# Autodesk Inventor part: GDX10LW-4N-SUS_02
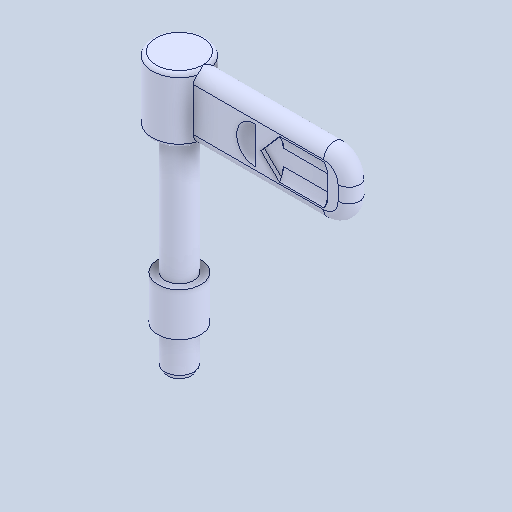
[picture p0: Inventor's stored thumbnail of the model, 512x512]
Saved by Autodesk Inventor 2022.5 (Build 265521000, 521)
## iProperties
Created: 2024-06
Part Number: GDX10LW-4N-SUS_02
Material: 一般
Document SubType Name: Modeling
Designer: ImaoCorp
Density: 1 g/cm^3
Appearance: 既定
Author: ImaoCorp
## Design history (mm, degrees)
feature "GDX10LW-4N-SUS_02"
node "ソリッド1"
